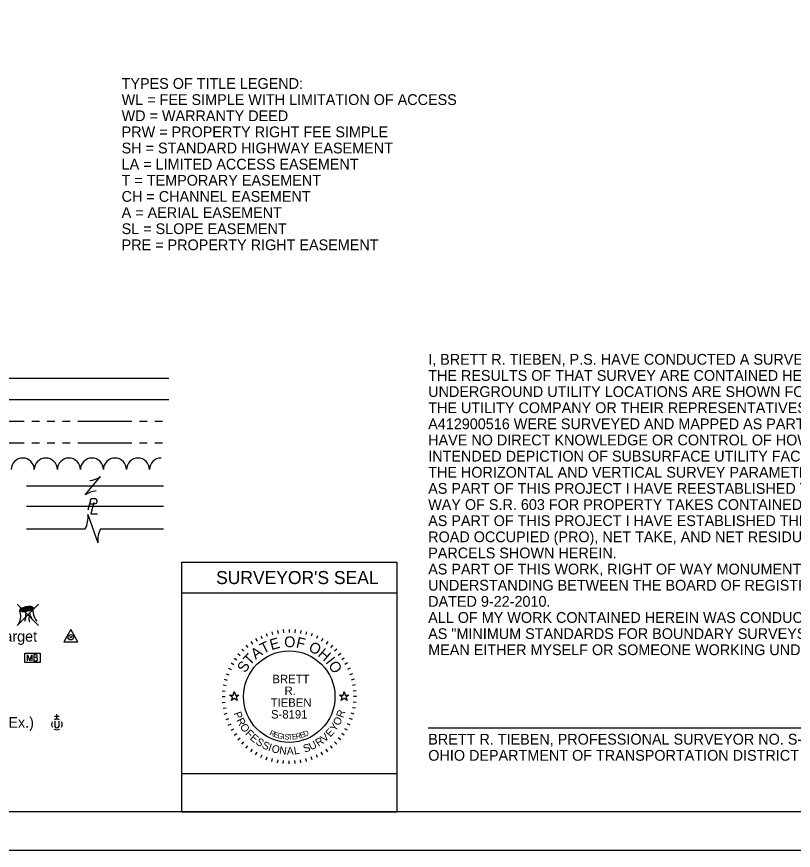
# Model space of a CAD drawing. Extents: x 0 to 34, y 0 to 22.
# Drawn here: x 12.32 to 22.43, y 0 to 10.85 of the extents above; entities that cross this region are included whole.
import ezdxf

# ---------------------------------------------------------------- set-up
doc = ezdxf.new("R2010")
doc.units = 0
for name, color, linetype in [('Default', 7, 'Continuous'), ('SH_Border', 7, 'Continuous'), ('SH_Cut_Line', 7, 'Continuous'), ('SH_Data', 7, 'Continuous'), ('SH_Seal', 7, 'Continuous'), ('SH_Text', 7, 'Continuous')]:
    doc.layers.add(name, color=color, linetype=linetype)

msp = doc.modelspace()

# ---------------------------------------------------------------- linework, layer by layer
at = {"layer": 'Default'}
msp.add_line((17.674, 1.594), (23.542, 1.594), dxfattribs=at)
at = {"layer": 'SH_Border'}
msp.add_lwpolyline([(1.5, 21.5), (33.5, 21.5), (33.5, 0.5), (1.5, 0.5)], close=True, dxfattribs=at)
at = {"layer": 'SH_Cut_Line'}
msp.add_lwpolyline([(0, 0), (34, 0), (34, 22), (0, 22)], close=True, dxfattribs=at)
at = {"layer": 'SH_Data'}
for p, q in [((14.464, 0.5), (14.464, 3.75)), ((14.464, 3.75), (17.264, 3.75)), ((17.264, 3.75), (17.264, 0.5)), ((14.464, 3.35), (17.264, 3.35)), ((14.464, 0.5), (17.264, 0.5))]:
    msp.add_line(p, q, dxfattribs=at)
msp.add_lwpolyline([(14.464, 0.5), (14.464, 1), (17.264, 1), (17.264, 0.5)], close=True, dxfattribs=at)
at = {"layer": 'SH_Seal'}
for p, q in [((15.564, 2.822), (15.578, 2.785)), ((15.637, 2.845), (15.648, 2.807)), ((15.712, 2.862), (15.719, 2.822)), ((15.787, 2.872), (15.791, 2.832)), ((15.864, 2.875), (15.864, 2.835)), ((15.94, 2.872), (15.937, 2.832)), ((16.016, 2.862), (16.009, 2.822)), ((16.09, 2.845), (16.08, 2.807)), ((16.163, 2.822), (16.149, 2.785)), ((15.362, 2.717), (15.385, 2.684)), ((15.426, 2.758), (15.446, 2.723)), ((15.494, 2.793), (15.511, 2.757)), ((16.234, 2.793), (16.217, 2.757)), ((16.301, 2.758), (16.281, 2.723)), ((16.366, 2.717), (16.343, 2.684)), ((15.245, 2.619), (15.273, 2.59)), ((15.301, 2.67), (15.327, 2.64)), ((16.426, 2.67), (16.4, 2.64)), ((16.482, 2.619), (16.454, 2.59)), ((15.147, 2.502), (15.18, 2.479)), ((15.193, 2.562), (15.224, 2.537)), ((16.534, 2.562), (16.503, 2.537)), ((16.581, 2.502), (16.548, 2.479)), ((15.106, 2.438), (15.141, 2.418)), ((16.622, 2.438), (16.587, 2.418)), ((15.042, 2.299), (15.079, 2.286)), ((15.071, 2.37), (15.107, 2.353)), ((16.657, 2.37), (16.621, 2.353)), ((16.686, 2.299), (16.648, 2.286)), ((15.019, 2.226), (15.057, 2.216)), ((16.709, 2.226), (16.67, 2.216)), ((14.992, 2.076), (15.032, 2.073)), ((15.002, 2.152), (15.041, 2.145)), ((16.725, 2.152), (16.686, 2.145)), ((16.735, 2.076), (16.696, 2.073)), ((14.989, 2), (15.029, 2)), ((16.739, 2), (16.699, 2)), ((14.992, 1.924), (15.032, 1.927)), ((15.002, 1.848), (15.041, 1.855)), ((16.725, 1.848), (16.686, 1.855)), ((16.735, 1.924), (16.696, 1.927)), ((15.019, 1.774), (15.057, 1.784)), ((16.709, 1.774), (16.67, 1.784)), ((15.042, 1.701), (15.079, 1.714)), ((15.071, 1.63), (15.107, 1.647)), ((16.657, 1.63), (16.621, 1.647)), ((16.686, 1.701), (16.648, 1.714)), ((15.106, 1.563), (15.141, 1.583)), ((15.147, 1.498), (15.18, 1.521)), ((16.581, 1.498), (16.548, 1.521)), ((16.622, 1.563), (16.587, 1.583)), ((15.193, 1.438), (15.224, 1.463)), ((16.534, 1.438), (16.503, 1.463)), ((15.245, 1.381), (15.273, 1.41)), ((15.301, 1.33), (15.327, 1.36)), ((15.362, 1.283), (15.385, 1.316)), ((16.366, 1.283), (16.343, 1.316)), ((16.426, 1.33), (16.4, 1.36)), ((16.482, 1.381), (16.454, 1.41)), ((15.426, 1.242), (15.446, 1.277)), ((15.494, 1.207), (15.511, 1.243)), ((15.564, 1.178), (15.578, 1.215)), ((15.637, 1.155), (15.648, 1.193)), ((16.09, 1.155), (16.08, 1.193)), ((16.163, 1.178), (16.149, 1.215)), ((16.234, 1.207), (16.217, 1.243)), ((16.301, 1.242), (16.281, 1.277)), ((15.712, 1.138), (15.719, 1.178)), ((15.787, 1.128), (15.791, 1.168)), ((15.864, 1.125), (15.864, 1.165)), ((15.94, 1.128), (15.937, 1.168)), ((16.016, 1.138), (16.009, 1.178))]:
    msp.add_line(p, q, dxfattribs=at)
for points in [[(15.087, 2.02), (15.134, 2.02), (15.149, 2.065), (15.163, 2.02), (15.21, 2.02), (15.172, 1.992), (15.187, 1.948), (15.149, 1.975), (15.111, 1.948), (15.125, 1.992)], [(16.517, 2.02), (16.564, 2.02), (16.579, 2.065), (16.593, 2.02), (16.64, 2.02), (16.602, 1.992), (16.617, 1.948), (16.579, 1.975), (16.541, 1.948), (16.555, 1.992)]]:
    msp.add_lwpolyline(points, close=True, dxfattribs=at)
msp.add_circle((15.864, 2), 0.595, dxfattribs=at)
at = {"layer": 'SH_Text'}
for p, q in [((10.813, 6.145), (14.296, 6.145)), ((10.813, 5.865), (14.296, 5.865)), ((11.713, 5.585), (12.413, 5.585)), ((12.513, 5.585), (12.613, 5.585)), ((12.713, 5.585), (12.813, 5.585)), ((12.913, 5.585), (13.013, 5.585)), ((13.113, 5.585), (13.813, 5.585)), ((13.913, 5.585), (14.013, 5.585)), ((14.113, 5.585), (14.213, 5.585)), ((11.713, 5.305), (12.413, 5.305)), ((12.513, 5.305), (12.613, 5.305)), ((12.713, 5.305), (12.813, 5.305)), ((12.913, 5.305), (13.013, 5.305)), ((13.113, 5.305), (13.813, 5.305)), ((13.913, 5.305), (14.013, 5.305)), ((14.113, 5.305), (14.213, 5.305)), ((13.208, 4.625), (13.408, 4.865)), ((12.443, 4.745), (14.225, 4.745)), ((13.308, 4.745), (13.308, 4.745)), ((12.443, 4.48), (14.225, 4.48)), ((13.266, 4.51), (13.331, 4.51)), ((13.306, 4.478), (13.306, 4.478)), ((13.243, 4.369), (13.373, 4.001)), ((12.443, 4.185), (13.208, 4.185)), ((13.308, 4.185), (13.308, 4.185)), ((13.408, 4.185), (14.225, 4.185)), ((12.321, 3.204), (12.599, 2.926)), ((12.599, 3.204), (12.321, 2.926)), ((12.46, 3.065), (12.46, 3.065)), ((12.46, 3.065), (12.46, 3.065)), ((12.522, 2.505), (12.522, 2.505)), ((12.871, 1.74), (12.807, 1.74)), ((12.839, 1.708), (12.839, 1.772)), ((12.812, 1.681), (12.812, 1.613)), ((12.839, 1.638), (12.839, 1.638)), ((12.866, 1.681), (12.866, 1.613))]:
    msp.add_line(p, q, dxfattribs=at)
for points in [[(13.245, 4.43), (13.284, 4.578), (13.336, 4.578)], [(13.319, 4.526), (13.28, 4.379), (13.367, 4.379)], [(12.457, 2.465), (12.457, 2.545), (12.486, 2.465), (12.513, 2.545), (12.513, 2.465)], [(12.573, 2.508), (12.576, 2.511), (12.578, 2.513), (12.579, 2.515), (12.58, 2.516), (12.581, 2.519), (12.582, 2.521), (12.583, 2.525), (12.583, 2.527), (12.583, 2.53), (12.582, 2.533), (12.581, 2.537), (12.579, 2.539), (12.576, 2.542), (12.573, 2.543), (12.572, 2.543), (12.569, 2.545), (12.538, 2.545), (12.538, 2.465), (12.573, 2.465), (12.577, 2.467), (12.581, 2.47), (12.584, 2.475), (12.586, 2.481), (12.587, 2.487), (12.587, 2.491), (12.585, 2.494), (12.583, 2.5), (12.58, 2.504), (12.573, 2.508), (12.538, 2.508)]]:
    msp.add_lwpolyline(points, dxfattribs=at)
for points in [[(12.93, 2.715), (13.11, 2.715), (13.02, 2.876)], [(12.422, 2.566), (12.622, 2.566), (12.622, 2.444), (12.422, 2.444)]]:
    msp.add_lwpolyline(points, close=True, dxfattribs=at)
for radius in [0.035, 0.008]:
    msp.add_circle((13.02, 2.773), radius, dxfattribs=at)
for centre, radius, start, end in [((12.395, 4.955), 0.15, 0.0098, 179.9926), ((12.695, 4.955), 0.15, 0.0098, 179.9926), ((12.995, 4.955), 0.15, 0.0098, 179.9926), ((13.295, 4.955), 0.15, 0.0098, 179.9926), ((13.595, 4.955), 0.15, 0.0098, 179.9926), ((13.895, 4.955), 0.15, 0.0098, 179.9926), ((14.195, 4.955), 0.15, 89.9955, 179.9926), ((13.25, 5.08), 0.267, 273.6945, 306.337), ((13.366, 4.41), 0.267, 93.6945, 126.337), ((13.33, 4.544), 0.0345, 270.471, 81.3281), ((12.911, 4.336), 0.334, 332.9422, 5.5848), ((13.705, 4.033), 0.334, 152.9422, 185.5848), ((12.741, 3.122), 0.215, 171.4106, 219.9194), ((12.169, 3.047), 0.2, 331.5338, 20.9269), ((12.184, 3.066), 0.253, 340.7938, 3.5481), ((12.786, 3.168), 0.316, 194.9653, 212.1216), ((12.656, 3.025), 0.182, 178.7926, 197.1224), ((12.839, 1.638), 0.07, 150.0184, 209.9816), ((12.839, 1.638), 0.07, 60.0184, 120.0157), ((12.839, 1.638), 0.07, 330.0184, 29.9816), ((12.839, 1.638), 0.07, 239.9843, 299.9816), ((12.839, 1.625), 0.03, 205.1924, 334.8076)]:
    msp.add_arc(centre, radius, start, end, dxfattribs=at)
for major_axis in [(0.0868, 0.0187), (0.0651, 0.0141), (0.0488, 0.0105), (0.0275, 0.0059), (0.0154, 0.0033)]:
    msp.add_ellipse((12.442, 3.14), major_axis=major_axis, ratio=0.36865, dxfattribs=at)

# ---------------------------------------------------------------- texts
at = {"layer": 'Default'}
for s, p in [('I, BRETT R. TIEBEN, P.S. HAVE CONDUCTED A SURVEY OF THE EXISTING CONDITIONS FOR THE OHIO DEPARTMENT OF TRANSPORTATION IN JUNE, 2024.', (17.673, 6.32)), ('THE RESULTS OF THAT SURVEY ARE CONTAINED HEREIN.', (17.673, 6.11)), ('UNDERGROUND UTILITY LOCATIONS ARE SHOWN FOR INFORMATION PURPOSES ONLY. THEIR LOCATION AS MARKED ON THE GROUND BY', (17.673, 5.9)), ('THE UTILITY COMPANY OR THEIR REPRESENTATIVES PER OHIO811 NUMBERS A412900491, A412900496, A412900499, A412900504 AND', (17.673, 5.69)), ('A412900516 WERE SURVEYED AND MAPPED AS PART OF THIS PROJECT. I FOLLOWED OHIO811 UTILITY DAMAGE PREVENTION LAWS AND', (17.673, 5.48)), ('HAVE NO DIRECT KNOWLEDGE OR CONTROL OF HOW THESE MARKS WERE PLACED, NOR KNOWLEDGE OF THE ACCURACY AS TO THEIR', (17.673, 5.27)), ('INTENDED DEPICTION OF SUBSURFACE UTILITY FACILITIES. SEE THE AFFIXED SURVEY PARAMETERS NOTE ON THE CENTERLINE PLATS FOR', (17.673, 5.06)), ('THE HORIZONTAL AND VERTICAL SURVEY PARAMETERS USED FOR THIS PROJECT.', (17.673, 4.85)), ('AS PART OF THIS PROJECT I HAVE REESTABLISHED THE LOCATIONS OF THE EXISTING BOUNDARY LINES AND CENTERLINE OF EXISTING RIGHT OF', (17.673, 4.64)), ('WAY OF S.R. 603 FOR PROPERTY TAKES CONTAINED HEREIN.', (17.673, 4.43)), ('AS PART OF THIS PROJECT I HAVE ESTABLISHED THE PROPOSED BOUNDARY LINES, CALCULATED THE GROSS TAKE, PRESENT', (17.673, 4.22)), ('ROAD OCCUPIED (PRO), NET TAKE, AND NET RESIDUE; AS WELL AS PREPARED THE LEGAL DESCRIPTIONS NECESSARY TO ACQUIRE THE', (17.673, 4.01)), ('PARCELS SHOWN HEREIN.', (17.673, 3.8)), ('AS PART OF THIS WORK, RIGHT OF WAY MONUMENTS WILL BE SET AT THE LOCATIONS SHOWN HEREIN PER THE MEMORANDUM OF', (17.673, 3.59)), ('UNDERSTANDING BETWEEN THE BOARD OF REGISTRATION FOR ENGINEERS AND SURVEYORS AND THE OHIO DEPARTMENT OF TRANSPORTATION', (17.673, 3.38)), ('DATED 9-22-2010.', (17.673, 3.17)), ('ALL OF MY WORK CONTAINED HEREIN WAS CONDUCTED IN ACCORDANCE WITH OHIO ADMINISTRATIVE CODE 4733-37 COMMONLY KNOWN', (17.673, 2.96)), ('AS "MINIMUM STANDARDS FOR BOUNDARY SURVEYS IN THE STATE OF OHIO" UNLESS SO NOTED. THE WORDS I AND MY AS USED HEREIN ARE T0', (17.673, 2.75)), ('MEAN EITHER MYSELF OR SOMEONE WORKING UNDER MY DIRECT SUPERVISION. ', (17.673, 2.54)), ('BRETT R. TIEBEN, PROFESSIONAL SURVEYOR NO. S-8191', (17.674, 1.376)), ('OHIO DEPARTMENT OF TRANSPORTATION DISTRICT THREE', (17.674, 1.166))]:
    msp.add_text(s, height=0.14, dxfattribs=at).set_placement(p)
at = {"layer": 'SH_Data'}
msp.add_text("SURVEYOR'S SEAL", height=0.17, dxfattribs=at).set_placement((14.912, 3.465))
at = {"layer": 'SH_Seal'}
for s, height, rotation, p in [('T', 0.14, 25.7167, (15.525, 2.552)), ('E', 0.14, 15.7571, (15.632, 2.604)), ('O', 0.14, 359.7812, (15.798, 2.644)), ('F', 0.14, 347.4362, (15.945, 2.642)), ('A', 0.14, 36.4747, (15.427, 2.478)), ('O', 0.14, 332.2586, (16.104, 2.602)), ('H', 0.14, 319.9136, (16.227, 2.536)), ('T', 0.14, 46.4344, (15.352, 2.396)), ('I', 0.14, 308.367, (16.33, 2.448)), ('S', 0.14, 57.1924, (15.292, 2.301)), ('O', 0.14, 303.1491, (16.366, 2.409)), ('P', 0.1, 289.7431, (15.139, 1.784)), ('R', 0.1, 70.983, (16.565, 1.717)), ('R', 0.1, 296.9802, (15.173, 1.693)), ('O', 0.1, 304.7158, (15.217, 1.608)), ('Y', 0.1, 55.5058, (16.464, 1.54)), ('O', 0.1, 62.7428, (16.514, 1.613)), ('F', 0.1, 312.956, (15.283, 1.516)), ('E', 0.1, 319.6885, (15.345, 1.45)), ('R', 0.07, 334.487, (15.601, 1.505)), ('E', 0.07, 341.04, (15.654, 1.48)), ('G', 0.07, 347.4752, (15.705, 1.462)), ('R', 0.07, 11.9184, (15.956, 1.447)), ('E', 0.07, 17.6836, (16.014, 1.46)), ('D', 0.07, 23.3052, (16.065, 1.477)), ('V', 0.1, 41.0316, (16.325, 1.401)), ('E', 0.1, 48.2687, (16.4, 1.467)), ('S', 0.1, 326.9255, (15.419, 1.389)), ('S', 0.1, 334.1626, (15.5, 1.337)), ('I', 0.07, 353.7858, (15.773, 1.447)), ('S', 0.07, 356.8926, (15.8, 1.443)), ('T', 0.07, 3.0061, (15.849, 1.439)), ('E', 0.07, 6.0117, (15.903, 1.441)), ('U', 0.1, 25.5604, (16.147, 1.299)), ('R', 0.1, 33.296, (16.245, 1.347)), ('I', 0.1, 341.3997, (15.583, 1.298)), ('O', 0.1, 345.1351, (15.626, 1.282)), ('N', 0.1, 353.3752, (15.73, 1.255)), ('A', 0.1, 1.1108, (15.833, 1.244)), ('L', 0.1, 8.3479, (15.93, 1.247)), ('S', 0.1, 18.3234, (16.064, 1.271))]:
    msp.add_text(s, height=height, rotation=rotation, dxfattribs=at).set_placement(p)
for s, p in [('BRETT', (15.645, 2.175)), ('R.', (15.803, 2.022)), ('TIEBEN', (15.622, 1.868)), ('S-8191', (15.627, 1.715))]:
    msp.add_text(s, height=0.11, dxfattribs=at).set_placement(p)
at = {"layer": 'SH_Text'}
for s, p in [('TYPES OF TITLE LEGEND:', (13.682, 9.91)), ('WL = FEE SIMPLE WITH LIMITATION OF ACCESS', (13.682, 9.7)), ('WD = WARRANTY DEED', (13.682, 9.49)), ('PRW = PROPERTY RIGHT FEE SIMPLE', (13.682, 9.28)), ('SH = STANDARD HIGHWAY EASEMENT', (13.682, 9.07)), ('LA = LIMITED ACCESS EASEMENT', (13.682, 8.86)), ('T = TEMPORARY EASEMENT', (13.682, 8.65)), ('CH = CHANNEL EASEMENT', (13.682, 8.44)), ('A = AERIAL EASEMENT', (13.682, 8.23)), ('SL = SLOPE EASEMENT', (13.682, 8.02)), ('PRE = PROPERTY RIGHT EASEMENT', (13.682, 7.81)), ('Wetland (Pr)         , Grass (Pr)            , Aerial Target    ', (8.296, 2.715)), ('Water Valve (Ex)         , Utility Valve Unknown (Ex.)', (8.296, 1.595))]:
    msp.add_text(s, height=0.14, dxfattribs=at).set_placement(p)

doc.saveas('drawing.dxf')
